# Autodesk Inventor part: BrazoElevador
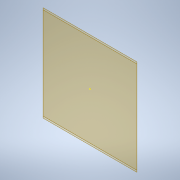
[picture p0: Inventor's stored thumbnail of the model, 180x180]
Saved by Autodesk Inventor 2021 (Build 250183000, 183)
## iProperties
Created: 2021-02
Part Number: BrazoElevador
Material: Genérico
Document SubType Name: Modeling
Designer: ATOUZA
Density: 1 g/cm^3
Appearance: Valor por defecto
Author: ATOUZA
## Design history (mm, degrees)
node "Plano de trabajo1"
node "Plano de trabajo2"
sketch "Boceto2"
  geometry: L1 (-18.63, 19)-(0.213, 19) reference; L2 (-21, 10.73)-(-21, 16.63) reference; L3 (-17.409, 7.139)-(-21, 10.73) reference; L4 (-16.75, -6.463)-(-16.75, 5.548) reference; L5 (-8.312, -14.902)-(-16.75, -6.463) reference; L6 (-4.213, -19)-(-5.402, -17.812) reference; L7 (14.63, -19)-(-4.213, -19) reference; L8 (17, -10.73)-(17, -16.63) reference; L9 (13.409, -7.139)-(17, -10.73) reference; L10 (12.75, 6.463)-(12.75, -5.548) reference; L11 (4.312, 14.902)-(12.75, 6.463) reference; L12 (0.213, 19)-(1.402, 17.812) reference; L13 (-21, 19)-(17, 19); L14 (17, 19)-(17, -19); L15 (17, -19)-(-21, -19); L16 (-21, -19)-(-21, 19); L17 (17, -19)-(47, -19); L18 (47, -19)-(47, 19); L19 (47, 19)-(17, 19); L20 (17, 19)-(17, -19); L21 (-21, 19)-(47, 19); L22 (47, 19)-(47, -19); L23 (47, -19)-(-21, -19); L24 (-21, -19)-(-21, 19); L25 (135.5, -17.5)-(135.5, 17.5) reference; L26 (135.5, 17.5)-(100.5, 17.5) reference; L27 (100.5, 17.5)-(100.5, -17.5) reference; L28 (100.5, -17.5)-(135.5, -17.5) reference; L29 (118, 17.5)-(118, -17.5); L30 (100.5, 0)-(135.5, 0); L31 (37, 19)-(37, -19); C1 r 3 at (-2, 0) reference; C2 r 2.5 at (-9.778, 7.778) reference; C3 r 2.5 at (5.778, -7.778) reference; C4 r 2.5 at (-9.778, 7.778) reference; C5 r 2.5 at (5.778, -7.778) reference; C6 r 2.5 at (5.778, 7.778) reference; C7 r 2.5 at (-9.778, -7.778) reference; C8 r 2.5 at (-9.778, 7.778); C9 r 2.5 at (5.778, -7.778); C10 r 2 at (37, 11); C11 r 2 at (37, -11); A1 r 25.25 centre (-2, 0) between (-18.63, 19) and (-21, 16.63) reference; A2 r 2.25 centre (-19, 5.548) between (-16.75, 5.548) and (-17.409, 7.139) reference; A3 r 2.25 centre (-7.5, -17) between (-5.402, -17.812) and (-8.312, -14.902) reference; A4 r 25.25 centre (-2, 0) between (14.63, -19) and (17, -16.63) reference; A5 r 2.25 centre (15, -5.548) between (12.75, -5.548) and (13.409, -7.139) reference; A6 r 2.25 centre (3.5, 17) between (1.402, 17.812) and (4.312, 14.902) reference
  constraints: 30 end point, 7 point on line, 6 parallel, 4 centre point, 4 midpoint, 4 perpendicular, 3 horizontal, 2 coincident
  dimensions: "d10" = 30 distance of L19.end L18.end; "d11" = 5 diameter of C8; "d12" = 5 diameter of C9; "d18" = 10 distance between parallel lines of L18 L31; "d19" = 38 distance of L31.start L31.end; "d20" = 4 diameter of C10; "d21" = 4 diameter of C11; "d22" = 8 distance from line of L21 C10.centre; "d23" = 8 distance from line of L23 C11.centre
extrude "Extrusión2" new body sketch "Boceto2" distance "d15" = 5; taper "d16" = 0 deg
fillet "Empalme1" dims "d17" = 4
node "Sólido1"
node "Referencia5"
node "Referencia6"
node "Referencia7"
node "Referencia8"
node "Referencia9"
feature "㿼"
